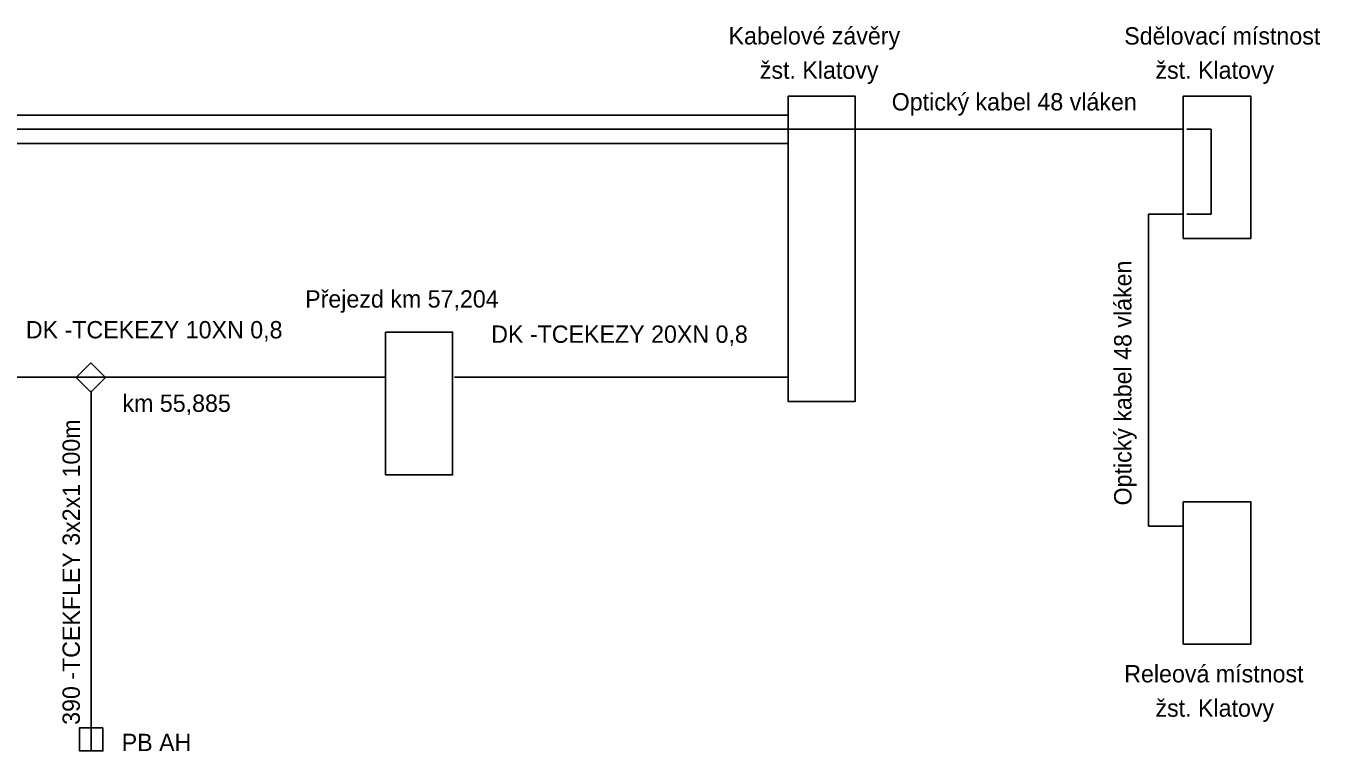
# Model space of a CAD drawing. Extents: x -544168 to -541853, y -1202572 to -1202265.
# Drawn here: x -542267.7 to -542081.3, y -1202394.9 to -1202290.3 of the extents above; entities that cross this region are included whole.
import ezdxf

# ---------------------------------------------------------------- set-up
doc = ezdxf.new("R2010")
doc.units = 0
doc.layers.add('_Popisové pole', color=7, linetype='Continuous')
doc.layers.add('Default', color=7, linetype='Continuous')

# ---------------------------------------------------------------- blocks, each defined once
blk = doc.blocks.new('SB11')
at = {"layer": 'Default'}
blk.add_lwpolyline([(-0.15, 0), (0.15, 0), (0.15, -0.3), (-0.15, -0.3)], close=True, dxfattribs=at)
blk.add_lwpolyline([(-0.15, 0), (0.15, 0), (0.15, -0.3), (-0.15, -0.3)], close=True, dxfattribs=at)

msp = doc.modelspace()

# ---------------------------------------------------------------- linework, layer by layer
at = {"layer": '_Popisové pole'}
for p, q in [((-542101, -1202305.26), (-544051.5, -1202305.26)), ((-542258.32, -1202342.98), (-542258.32, -1202392)), ((-542258.32, -1202391.56), (-542260, -1202391.56)), ((-542258.32, -1202391.56), (-542258.32, -1202394.9)), ((-542258.32, -1202394.9), (-542258.32, -1202391.56))]:
    msp.add_line(p, q, dxfattribs=at)
msp.add_lwpolyline([(-542256.64, -1202391.56), (-542260, -1202391.56), (-542260, -1202394.9), (-542256.64, -1202394.9)], close=True, dxfattribs=at)
msp.add_lwpolyline([(-542260, -1202391.56), (-542260, -1202394.9), (-542258.32, -1202394.9)], dxfattribs=at)
at = {"layer": 'Default'}
for p, q in [((-542976.94, -1202303.24), (-542157.92, -1202303.24)), ((-542100.5, -1202305.26), (-542097, -1202305.26)), ((-542097, -1202305.26), (-542097, -1202317.5)), ((-542976.94, -1202307.31), (-542157.92, -1202307.31)), ((-542101, -1202317.5), (-542106, -1202317.5)), ((-542106, -1202317.5), (-542106, -1202362.5)), ((-542097, -1202317.5), (-542100.5, -1202317.5)), ((-542284.41, -1202341.02), (-542216, -1202341.02)), ((-542206, -1202341.02), (-542158, -1202341.02)), ((-542106, -1202362.5), (-542101, -1202362.5))]:
    msp.add_line(p, q, dxfattribs=at)
for points in [[(-542157.92, -1202300.5), (-542148.26, -1202300.5), (-542148.26, -1202344.5), (-542157.92, -1202344.5)], [(-542101, -1202300.5), (-542091.26, -1202300.5), (-542091.26, -1202321), (-542101, -1202321)], [(-542215.92, -1202334.49), (-542206.26, -1202334.49), (-542206.26, -1202355.1), (-542215.92, -1202355.1)], [(-542101, -1202359), (-542091.26, -1202359), (-542091.26, -1202379.5), (-542101, -1202379.5)]]:
    msp.add_lwpolyline(points, close=True, dxfattribs=at)

# ---------------------------------------------------------------- block references
at = {"layer": '_Popisové pole', "xscale": 10.000000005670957, "yscale": 10.000000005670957, "rotation": 44.99999999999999}
msp.add_blockref('SB11', (-542259.44, -1202340), dxfattribs=at)

# ---------------------------------------------------------------- texts
at = {"layer": '_Popisové pole'}
for s, rotation, p in [('km 55,885', 0.0018, (-542253.82, -1202346.01)), ('390 -TCEKFLEY 3x2x1 100m', 90, (-542259.96, -1202391.14))]:
    msp.add_text(s, height=2.5, rotation=rotation, dxfattribs=at).set_placement(p)
msp.add_text('PB AH', height=2.5, dxfattribs=at).set_placement((-542253.93, -1202394.93))
at = {"layer": 'Default'}
for s, p in [('Kabelové závěry', (-542166.5, -1202293.02)), ('Sdělovací místnost', (-542109.5, -1202293.04)), ('žst. Klatovy', (-542162, -1202297.97)), ('žst. Klatovy', (-542105, -1202297.97)), ('Optický kabel 48 vláken', (-542143, -1202302.54)), ('Přejezd km 57,204', (-542227.5, -1202330.97)), ('Releová místnost', (-542109.5, -1202385.02)), ('žst. Klatovy', (-542105, -1202389.97))]:
    msp.add_text(s, height=2.5, dxfattribs=at).set_placement(p)
for s, rotation, p in [('Optický kabel 48 vláken', 90, (-542108.46, -1202359.5)), ('DK -TCEKEZY 10XN 0,8 ', 0.0018, (-542267.74, -1202335.41)), ('DK -TCEKEZY 20XN 0,8  ', 0.0018, (-542200.7, -1202336.05))]:
    msp.add_text(s, height=2.5, rotation=rotation, dxfattribs=at).set_placement(p)

doc.saveas('drawing.dxf')
